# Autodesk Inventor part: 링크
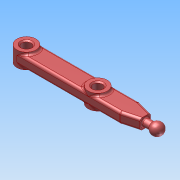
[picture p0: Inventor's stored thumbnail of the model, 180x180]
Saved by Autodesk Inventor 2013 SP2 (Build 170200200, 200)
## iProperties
Created: 2025-07
Part Number: 링크
Material: Generic
Document SubType Name: Modeling
Designer: a
Density: 1 g/cm^3
변환 표준: STEP AP214IS
전처리기: Build: 200, Release: 2013 SP2 Update 6 - Date: Thu 07/17/2014
전송 단위: 밀리미터
불확실성: 0.01
Author: a
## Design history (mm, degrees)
node "링크1"
node "솔리드1"
node "기준1"
